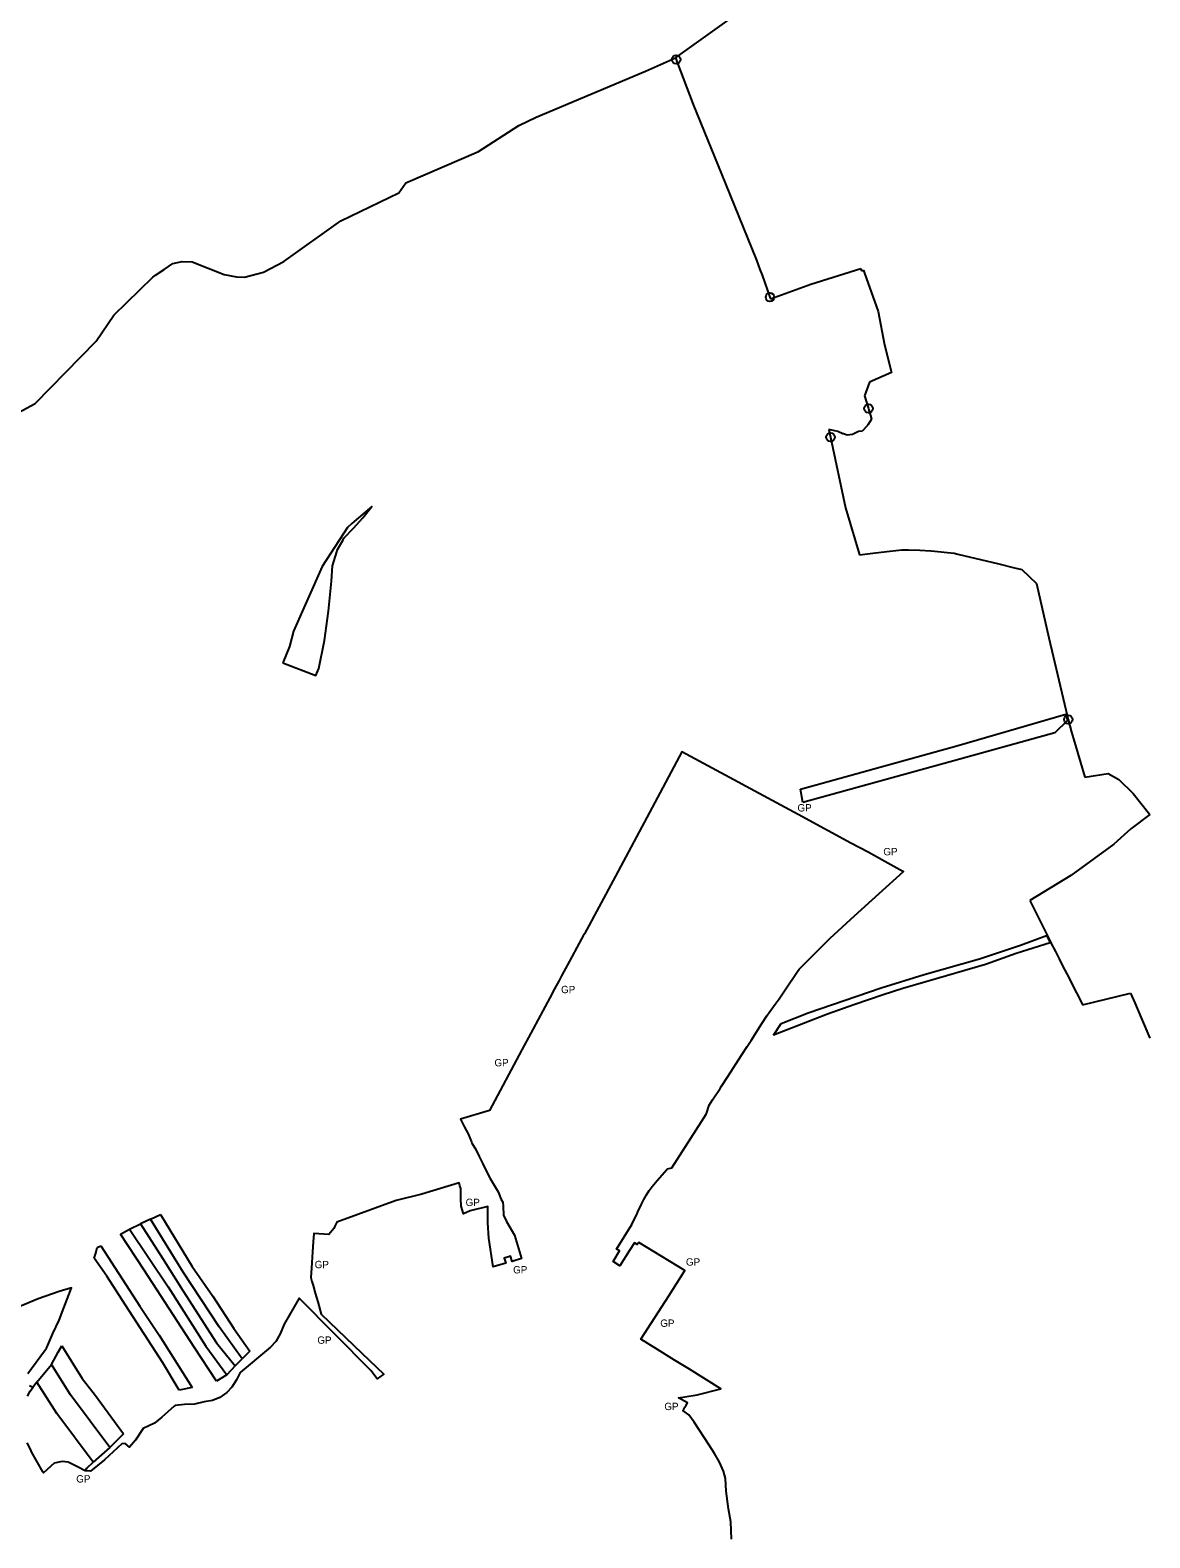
# Model space of a CAD drawing. Extents: x -534397 to -527742, y -1181460 to -1175250.
# Drawn here: x -531038 to -529730, y -1178187 to -1176425 of the extents above; entities that cross this region are included whole.
import ezdxf

# ---------------------------------------------------------------- set-up
doc = ezdxf.new("R2010")
doc.units = 0
for name, color, linetype in [('Hranice obcí', 7, 'Continuous'), ('Hranice parcel', 7, 'Continuous'), ('Hranice státní', 7, 'Continuous')]:
    doc.layers.add(name, color=color, linetype=linetype)

msp = doc.modelspace()

# ---------------------------------------------------------------- linework, layer by layer
at = {"layer": 'Hranice obcí'}
for p, q in [((-529955.2, -1177261.4), (-529827.8, -1177224.5)), ((-529827.8, -1177224.5), (-529826, -1177231.6)), ((-529826, -1177231.6), (-529841, -1177246)), ((-529841, -1177246), (-529951.9, -1177276.8)), ((-530137.9, -1177312.1), (-529955.2, -1177261.4)), ((-529951.9, -1177276.8), (-530135.2, -1177327.7)), ((-530135.2, -1177327.7), (-530137.9, -1177312.1)), ((-529881, -1177494.1), (-529850.7, -1177483)), ((-529850.7, -1177483), (-529846.3, -1177491.6)), ((-529928.7, -1177510.2), (-529881, -1177494.1)), ((-529885.9, -1177504), (-529921.7, -1177516.7)), ((-529846.3, -1177491.6), (-529885.9, -1177504)), ((-529993.5, -1177528.5), (-529928.7, -1177510.2)), ((-529921.7, -1177516.7), (-529991.4, -1177537.1)), ((-530043.9, -1177544.2), (-529993.5, -1177528.5)), ((-529991.4, -1177537.1), (-530018.6, -1177544.8)), ((-530129.1, -1177573.2), (-530043.9, -1177544.2)), ((-530041.4, -1177552.3), (-530075.8, -1177563.9)), ((-530018.6, -1177544.8), (-530041.4, -1177552.3)), ((-530106.4, -1177574.8), (-530169.6, -1177599.2)), ((-530160.7, -1177585.7), (-530129.1, -1177573.2)), ((-530075.8, -1177563.9), (-530106.4, -1177574.8)), ((-530169.6, -1177599.2), (-530160.7, -1177585.7)), ((-530921.7, -1177826.1), (-530909.2, -1177819.9)), ((-530897.5, -1177814.2), (-530909.2, -1177819.9)), ((-530909.2, -1177819.9), (-530883.5, -1177859.7)), ((-530897.5, -1177814.2), (-530885.5, -1177808.7)), ((-530859.3, -1177876.3), (-530897.5, -1177814.2)), ((-530885.5, -1177808.7), (-530848.6, -1177869.8)), ((-530932.3, -1177831.9), (-530921.7, -1177826.1)), ((-530904.6, -1177873.9), (-530932.3, -1177831.9)), ((-530921.7, -1177826.1), (-530876.6, -1177893.2)), ((-530963.1, -1177859.9), (-530961.2, -1177854.1)), ((-530961.2, -1177854.1), (-530959.5, -1177847.6)), ((-530959.5, -1177847.6), (-530955.5, -1177845.6)), ((-530955.5, -1177845.6), (-530909.8, -1177915.9)), ((-530846.5, -1177963.9), (-530904.6, -1177873.9)), ((-530883.5, -1177859.7), (-530859.4, -1177897.8)), ((-530817.1, -1177940.2), (-530859.3, -1177876.3)), ((-530848.6, -1177869.8), (-530824.4, -1177904.4)), ((-530876.6, -1177893.2), (-530832.7, -1177962.7)), ((-530859.4, -1177897.8), (-530820.4, -1177958.8)), ((-530824.4, -1177904.4), (-530800.1, -1177942.1)), ((-530883.1, -1177982.2), (-530926.6, -1177914.9)), ((-530909.8, -1177915.9), (-530887.1, -1177950)), ((-530790.4, -1177977.3), (-530817.1, -1177940.2)), ((-530800.1, -1177942.1), (-530781.4, -1177968.7)), ((-531005.3, -1177969.8), (-531001, -1177962.2)), ((-531001, -1177962.2), (-530977.1, -1178000.3)), ((-530887.1, -1177950), (-530848.5, -1178010.8)), ((-530820.1, -1178003.7), (-530846.5, -1177963.9)), ((-530832.7, -1177962.7), (-530808, -1177996.1)), ((-530820.4, -1177958.8), (-530798.3, -1177985.8)), ((-531013.1, -1177984.2), (-531005.3, -1177969.8)), ((-530863.9, -1178014.1), (-530883.1, -1177982.2)), ((-530798.3, -1177985.8), (-530790.4, -1177977.3)), ((-530781.4, -1177968.7), (-530790.4, -1177977.3)), ((-531030.2, -1178004.9), (-531013.1, -1177984.2)), ((-530990.8, -1178019.4), (-531013.1, -1177984.2)), ((-530977.1, -1178000.3), (-530961.6, -1178020.3)), ((-530808, -1177996.1), (-530820.1, -1178003.7)), ((-530798.3, -1177985.8), (-530808, -1177996.1)), ((-531031.8, -1178006.8), (-531034.8, -1178011.1)), ((-531030.2, -1178004.9), (-531031.8, -1178006.8)), ((-531006.6, -1178041.4), (-531030.2, -1178004.9)), ((-530848.5, -1178010.8), (-530863.9, -1178014.1)), ((-530944.7, -1178081.2), (-530990.8, -1178019.4)), ((-530961.6, -1178020.3), (-530928.8, -1178065)), ((-530964.2, -1178098.2), (-531006.6, -1178041.4)), ((-530928.8, -1178065), (-530944.7, -1178081.2)), ((-530944.7, -1178081.2), (-530964.2, -1178098.2)), ((-530973.8, -1178108.2), (-530971.7, -1178105.4)), ((-530971.7, -1178105.4), (-530964.2, -1178098.2))]:
    msp.add_line(p, q, dxfattribs=at)
msp.add_lwpolyline([(-530742.6, -1177164.3), (-530704.2, -1177179), (-530700.5, -1177171.1), (-530694, -1177138.1), (-530689.4, -1177104), (-530685.9, -1177069), (-530684.9, -1177051.2), (-530679.7, -1177034.5), (-530679.2, -1177032.8), (-530672.4, -1177020.7), (-530671.3, -1177018.8), (-530660.3, -1177006.9), (-530649.2, -1176995), (-530638.7, -1176981.6), (-530662, -1177001.7), (-530667.3, -1177006.3), (-530696.6, -1177051.9), (-530730.2, -1177127.5), (-530735, -1177145.4)], close=True, dxfattribs=at)
msp.add_lwpolyline([(-530926.6, -1177914.9), (-530948.3, -1177880.9), (-530963.1, -1177859.9)], dxfattribs=at)
at = {"layer": 'Hranice parcel'}
for p, q in [((-530318.9, -1176473), (-530284.1, -1176457.5)), ((-530284.1, -1176457.5), (-530284.1, -1176457.5)), ((-530284.1, -1176457.5), (-530283.3, -1176459.5)), ((-530283.3, -1176459.5), (-530282.5, -1176461.7)), ((-530282.5, -1176461.7), (-530263.4, -1176512.2)), ((-530446.8, -1176526.9), (-530318.9, -1176473)), ((-530263.4, -1176512.2), (-530225.6, -1176604.6)), ((-530514, -1176566.9), (-530467, -1176536.7)), ((-530467, -1176536.7), (-530446.8, -1176526.9)), ((-530599.2, -1176603.6), (-530514, -1176566.9)), ((-530607.3, -1176615.1), (-530599.2, -1176603.6)), ((-530225.6, -1176604.6), (-530189.3, -1176694)), ((-530675.1, -1176648), (-530607.3, -1176615.1)), ((-530741.7, -1176695.5), (-530675.1, -1176648)), ((-530871.1, -1176697.9), (-530860.2, -1176695.4)), ((-530860.2, -1176695.4), (-530848.6, -1176695.9)), ((-530848.6, -1176695.9), (-530811.1, -1176710.7)), ((-530765.3, -1176707.8), (-530741.7, -1176695.5)), ((-530189.3, -1176694), (-530185.4, -1176704.7)), ((-530940.3, -1176758.1), (-530894.7, -1176713.6)), ((-530894.7, -1176713.6), (-530891.4, -1176711.4)), ((-530891.4, -1176711.4), (-530881.5, -1176704.8)), ((-530881.5, -1176704.8), (-530871.1, -1176697.9)), ((-530811.1, -1176710.7), (-530796.7, -1176713.4)), ((-530796.7, -1176713.4), (-530787.5, -1176713.6)), ((-530787.5, -1176713.6), (-530765.3, -1176707.8)), ((-530185.4, -1176704.7), (-530182.9, -1176711.6)), ((-530182.9, -1176711.6), (-530173.6, -1176737.1)), ((-530125.8, -1176721.9), (-530067.5, -1176703.8)), ((-530067.5, -1176703.8), (-530067.4, -1176704)), ((-530067.4, -1176704), (-530066.6, -1176706.3)), ((-530066.6, -1176706.3), (-530064.4, -1176705.6)), ((-530064.4, -1176705.6), (-530063.1, -1176709.2)), ((-530063.1, -1176709.2), (-530047.3, -1176753.9)), ((-530173, -1176738.9), (-530125.8, -1176721.9)), ((-530173.6, -1176737.1), (-530173, -1176738.9)), ((-530960.8, -1176788.4), (-530940.3, -1176758.1)), ((-530047.3, -1176753.9), (-530039.7, -1176792.9)), ((-531032.1, -1176861.3), (-530960.8, -1176788.4)), ((-530039.7, -1176792.9), (-530031.6, -1176825.2)), ((-530057.4, -1176836.6), (-530063, -1176852.4)), ((-530031.6, -1176825.2), (-530057.4, -1176836.6)), ((-530063, -1176852.4), (-530058.6, -1176867.2)), ((-531051.5, -1176871.9), (-531032.1, -1176861.3)), ((-530058.6, -1176867.2), (-530058, -1176869.3)), ((-530058, -1176869.3), (-530057.5, -1176871)), ((-530057.5, -1176871), (-530055, -1176879.5)), ((-530059.6, -1176887), (-530066, -1176893.7)), ((-530058.9, -1176885.8), (-530059.6, -1176887)), ((-530055, -1176879.5), (-530058.9, -1176885.8)), ((-530094.4, -1176894), (-530104.7, -1176891.9)), ((-530104.7, -1176891.9), (-530102.9, -1176900.7)), ((-530102.9, -1176900.7), (-530085.4, -1176983.2)), ((-530088.4, -1176896.8), (-530094.4, -1176894)), ((-530087.9, -1176896.9), (-530088.4, -1176896.8)), ((-530083.6, -1176898.2), (-530087.9, -1176896.9)), ((-530077.2, -1176897.5), (-530083.6, -1176898.2)), ((-530070.2, -1176894), (-530077.2, -1176897.5)), ((-530066, -1176893.7), (-530070.2, -1176894)), ((-530085.4, -1176983.2), (-530069.2, -1177038.1)), ((-530069.2, -1177038.1), (-530053.3, -1177036.2)), ((-530053.3, -1177036.2), (-530037, -1177034.3)), ((-530037, -1177034.3), (-530019.4, -1177032.2)), ((-530019.4, -1177032.2), (-530011.6, -1177032.4)), ((-530011.6, -1177032.4), (-529998.5, -1177032.9)), ((-529998.5, -1177032.9), (-529985.6, -1177033.3)), ((-529985.6, -1177033.3), (-529985.2, -1177033.3)), ((-529985.2, -1177033.3), (-529958.3, -1177036.4)), ((-529958.3, -1177036.4), (-529954.1, -1177037.4)), ((-529954.1, -1177037.4), (-529906.4, -1177048.8)), ((-529906.4, -1177048.8), (-529887.8, -1177053.2)), ((-529887.8, -1177053.2), (-529879.4, -1177055.2)), ((-529879.4, -1177055.2), (-529862.4, -1177071.6)), ((-529862.4, -1177071.6), (-529847.7, -1177135.2)), ((-529847.7, -1177135.2), (-529825.9, -1177227.5)), ((-529825.9, -1177227.5), (-529825.1, -1177230.6)), ((-529825.1, -1177230.6), (-529821.4, -1177245.3)), ((-529821.4, -1177245.3), (-529819, -1177253.2)), ((-529819, -1177253.2), (-529805.9, -1177297.8)), ((-529805.9, -1177297.8), (-529778.4, -1177293.8)), ((-529778.4, -1177293.8), (-529766, -1177300.8)), ((-529766, -1177300.8), (-529749.2, -1177316.9)), ((-529749.2, -1177316.9), (-529729.9, -1177341.4)), ((-529729.9, -1177341.4), (-529752.2, -1177358.3)), ((-529752.2, -1177358.3), (-529771.9, -1177376.2)), ((-529771.9, -1177376.2), (-529794.9, -1177392.8)), ((-529794.9, -1177392.8), (-529822, -1177412.7)), ((-529822, -1177412.7), (-529870.2, -1177441.9)), ((-529870.2, -1177441.9), (-529849.7, -1177482.7)), ((-529849.7, -1177482.7), (-529845.1, -1177492.1)), ((-529845.1, -1177492.1), (-529840.2, -1177501.7)), ((-529840.2, -1177501.7), (-529835.9, -1177510)), ((-529835.9, -1177510), (-529831.7, -1177518.3)), ((-529831.7, -1177518.3), (-529827, -1177527.5)), ((-529827, -1177527.5), (-529815.5, -1177549.9)), ((-529815.5, -1177549.9), (-529810.6, -1177559.5)), ((-529810.6, -1177559.5), (-529808.4, -1177563.9)), ((-529808.4, -1177563.9), (-529752.4, -1177550.4)), ((-529752.4, -1177550.4), (-529747.5, -1177561.6)), ((-529747.5, -1177561.6), (-529740, -1177579)), ((-529740, -1177579), (-529729.8, -1177602.7))]:
    msp.add_line(p, q, dxfattribs=at)
for points in [[(-530218.7, -1178188.2), (-530219.4, -1178168.1), (-530222.1, -1178152.9), (-530224.7, -1178132), (-530225.6, -1178117.2), (-530228.1, -1178108.9), (-530232.4, -1178098.2), (-530238.3, -1178088.1), (-530244.7, -1178078.4), (-530262.3, -1178051.4), (-530268.4, -1178043), (-530275.4, -1178038), (-530274.4, -1178036.3), (-530273.1, -1178034.1), (-530271.7, -1178031.6), (-530270.1, -1178028.9), (-530280.3, -1178023.2), (-530273.1, -1178022), (-530258.8, -1178019.4), (-530231, -1178012.4), (-530267.7, -1177989.6), (-530285.1, -1177978.9), (-530305.2, -1177966.7), (-530324.3, -1177954.7), (-530291.9, -1177903.8), (-530273.1, -1177874.2), (-530327, -1177841.4), (-530328.6, -1177843.9), (-530331.9, -1177841.9), (-530337.6, -1177850.9), (-530349.1, -1177868.9), (-530356.8, -1177863.9), (-530349.3, -1177851.5), (-530352.8, -1177849.4), (-530335.2, -1177820.6), (-530331.7, -1177813.8), (-530329.3, -1177809), (-530327.9, -1177805.6), (-530323.7, -1177796.6), (-530321, -1177791.3), (-530318, -1177786), (-530314.9, -1177781), (-530311.4, -1177776.1), (-530305.6, -1177769.2), (-530294.1, -1177756.1), (-530293.2, -1177755.6), (-530288.4, -1177754.4), (-530253.6, -1177700.4), (-530248.3, -1177691.8), (-530247.8, -1177690.8), (-530244.6, -1177681.1), (-530242.6, -1177677.9), (-530240.6, -1177674.9), (-530231.9, -1177661.6), (-530230.3, -1177659.1), (-530222.8, -1177647.5), (-530206.7, -1177622.6), (-530200.2, -1177612.6), (-530198.6, -1177610.2), (-530195.7, -1177605.6), (-530183.2, -1177585.8), (-530177.4, -1177576.6), (-530174.5, -1177572.7), (-530167.6, -1177563.1), (-530163, -1177556.7), (-530155.9, -1177546.2), (-530141.5, -1177525), (-530139.6, -1177522.4), (-530138, -1177520.8), (-530109.2, -1177491.9), (-530105.6, -1177488.3), (-530103.4, -1177486.1), (-530074.8, -1177460.1), (-530045.9, -1177433.7), (-530017.7, -1177408), (-530018.4, -1177408.2), (-530036, -1177398.5), (-530039.4, -1177396.6), (-530059.1, -1177385.7), (-530079, -1177374.9), (-530132, -1177346.3), (-530135.6, -1177344.4), (-530276.6, -1177268.4), (-530311.3, -1177333.4), (-530354.2, -1177413.5), (-530390.5, -1177481), (-530391.8, -1177483.2), (-530393.7, -1177486.7), (-530396.4, -1177491.9), (-530407.7, -1177512.9), (-530417, -1177530.2), (-530419.8, -1177535.3), (-530425.2, -1177545.3), (-530430.8, -1177555.7), (-530441.7, -1177576), (-530453, -1177597), (-530463.4, -1177616.4), (-530501.4, -1177687.4), (-530535, -1177697.6), (-530530.8, -1177705.9), (-530526.3, -1177714.8), (-530522.5, -1177724.1), (-530521.9, -1177725.6), (-530517.7, -1177732.3), (-530513.4, -1177741), (-530509.1, -1177749.8), (-530505, -1177757.9), (-530500.6, -1177766.8), (-530491.2, -1177782.3), (-530487.7, -1177791.4), (-530485.8, -1177794.5), (-530485.5, -1177799.1), (-530484.8, -1177809.5), (-530481.5, -1177817.2), (-530472.1, -1177833.2), (-530463.9, -1177860.3), (-530473.8, -1177863.2), (-530474.9, -1177863.6), (-530476.7, -1177857.7), (-530484.2, -1177859.9), (-530482.4, -1177865.8), (-530496.9, -1177870), (-530502.2, -1177836.4), (-530503.4, -1177818.6), (-530503.3, -1177799.5), (-530523.7, -1177804.7), (-530531.8, -1177807.9), (-530534.4, -1177799), (-530534.6, -1177790), (-530534.9, -1177778.6), (-530535.9, -1177775.2), (-530536.9, -1177771.8), (-530580.4, -1177785.2), (-530610.2, -1177792.4), (-530679.6, -1177817.7), (-530682, -1177822.6), (-530683.3, -1177825.2), (-530688.9, -1177832.1), (-530706.6, -1177831.2), (-530707.2, -1177840.9), (-530707.6, -1177846.6), (-530708, -1177852.6), (-530708.4, -1177858.6), (-530708.9, -1177865), (-530709.3, -1177871.7), (-530709.7, -1177876.7), (-530710.1, -1177882.6), (-530708.7, -1177887.3), (-530707.4, -1177891.8), (-530704.9, -1177900.6), (-530702, -1177910.8), (-530697.8, -1177925.2), (-530650.4, -1177970.8), (-530624.9, -1177995.3), (-530628.4, -1177997.8), (-530632.5, -1178000.7), (-530640.1, -1177991.1), (-530723.5, -1177906.7), (-530741, -1177937.1), (-530745.7, -1177948.4), (-530750.8, -1177957.3), (-530757.2, -1177963.9), (-530792.5, -1177993.6), (-530796.8, -1178001.9), (-530802.3, -1178010.4), (-530808, -1178017), (-530816.3, -1178022.6), (-530824.9, -1178026), (-530834.6, -1178027.8), (-530846, -1178030.5), (-530857.8, -1178030.9), (-530868.7, -1178032), (-530869.7, -1178032.9), (-530877.2, -1178039.4), (-530884.2, -1178045.5), (-530892.6, -1178052.7), (-530905.9, -1178059), (-530914.9, -1178072.4), (-530921.7, -1178080.6), (-530926.8, -1178076.5), (-530930.9, -1178076.7), (-530950.9, -1178095.4), (-530967.4, -1178108.8), (-530973.8, -1178108.2), (-530982.7, -1178103.7), (-530993.5, -1178098.3), (-531000.4, -1178097.3), (-531009.7, -1178099.5), (-531022.5, -1178110.7), (-531023.2, -1178109.5), (-531036.2, -1178086.2), (-531037.3, -1178084), (-531041.4, -1178075.8)], [(-531040.5, -1177994.8), (-531026.6, -1177975.7), (-531018.9, -1177964.9), (-531018.6, -1177964.3), (-531011.3, -1177947.7), (-531004, -1177932.2), (-530998.6, -1177918), (-530992.8, -1177902.8), (-530989.8, -1177894.6), (-531004.2, -1177898.7), (-531028.6, -1177907.2), (-531117.4, -1177944.3)], [(-531040.9, -1178021.2), (-531037.8, -1178015.3), (-531034.8, -1178011.1), (-531036.3, -1178010.2), (-531038.8, -1178008.9)]]:
    msp.add_lwpolyline(points, dxfattribs=at)
at = {"layer": 'Hranice státní'}
msp.add_line((-530284.1, -1176457.5), (-529399, -1175825.4), dxfattribs=at)
for centre in [(-530283.3, -1176459.5), (-530173.6, -1176737.1), (-530058.6, -1176867.2), (-530102.9, -1176900.7), (-529825.1, -1177230.6)]:
    msp.add_circle(centre, 4.99, dxfattribs=at)

# ---------------------------------------------------------------- texts
at = {"layer": 'Hranice parcel'}
for p in [(-530141.5, -1177338), (-530041.2, -1177389.2), (-530417.7, -1177550.3), (-530495.5, -1177635.8), (-530529.2, -1177799), (-530705.5, -1177871.6), (-530473.7, -1177877.7), (-530271.8, -1177868.6), (-530301.8, -1177940.1), (-530702.4, -1177959.9), (-530297, -1178037.4), (-530984.1, -1178122)]:
    msp.add_text('GP', height=8.59, dxfattribs=at).set_placement(p)

doc.saveas('drawing.dxf')
